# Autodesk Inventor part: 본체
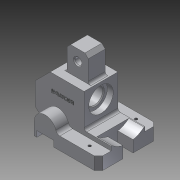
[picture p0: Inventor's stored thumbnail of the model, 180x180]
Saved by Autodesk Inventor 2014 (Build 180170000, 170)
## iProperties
Created: 2016-11
Part Number: 본체
Material: Aluminum 6061
Document SubType Name: Modeling
Designer: user
Density: 2.71 g/cm^3
Appearance: Aluminum - Flat
Author: user
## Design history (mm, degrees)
sketch "Sketch2"
  geometry: L1 (0, 0)-(63, 0); L2 (-13, 15)-(13, 15); L3 (-13, 15)-(-13, 0); L4 (0, 0)-(-13, 0); L5 (-10, 0)-(-10, 7); L6 (-10, 7)-(10, 7); L7 (10, 7)-(10, 0); L8 (13, 15)-(38.139, 15); L9 (-13, 0)-(-10, 0); L10 (63, 0)-(63, 15); L11 (38.139, 15)-(63, 15); A1 r 13 centre (0, 15) between (13, 15) and (-13, 15); 2 further points
  constraints: 22 end point, 7 perpendicular, 2 midpoint, 2 point on circle, 2 point on line, 1 centre point, 1 coincident, 1 collinear, 1 horizontal, 1 parallel, 1 tangent, 1 vertical alignment
  dimensions: "d0" = 26 diameter of A1; "d1" = 15 distance of L1.start A1.centre; "d2" = 7 distance of L5.start L5.end; "d3" = 20 distance of L5.end L6.end; "d4" = 63 distance of L1.end L1.start; "d5" = 15 distance of L1.end L10.end; "d6" = 3 distance between parallel lines of L5 L3
extrude "Extrusion1" new body sketch "Sketch2" stored distance "d7" = 70; taper "d8" = 0 deg
fillet "Fillet1" dims "d9" = 5
sketch "Sketch3"
  geometry: L1 (17.292, 15)-(63, 15) reference; L2 (63, 15)-(63, 0) reference; L3 (-13, 0)-(-13, 15) reference; L4 (63, 15)-(63, 20); L5 (-27, 12)-(-27, 42); L6 (31, 20)-(31, 60); L7 (26, 42)-(26, 60); L8 (-9, 60)-(31, 60); L9 (63, 0)-(10, 0) reference; L10 (-27, 12)-(-13, 12); L11 (-27, 42)-(31, 42); L12 (-27, 42)-(-9, 60); L13 (63, 15)-(17.292, 15) reference; L14 (31, 20)-(63, 20); A1 r 13 centre (0, 15) between (12.488, 18.611) and (-13, 15) reference; A2 r 5 centre (17.292, 20) between (12.488, 18.611) and (17.292, 15) reference; 3 further points
  constraints: 18 end point, 7 parallel, 5 point on line, 1 horizontal alignment, 1 perpendicular
  dimensions: "d10" = 5 distance of L4.end L1.end; "d11" = 90 distance between parallel lines of L2 L5; "d12" = 58 distance between parallel lines of L6 L5; "d13" = 5 distance between parallel lines of L6 L7; "d14" = 60 distance between parallel lines of L9 L8; "d15" = 48 distance between parallel lines of L10 L8; "d16" = 30 distance between parallel lines of L11 L10; "d17" = 45 deg angle of L12 L8
extrude "Extrusion2" join sketch "Sketch3" stored distance "d18" = 40; taper "d19" = 0 deg
chamfer "Chamfer1" distance "d20" = 4; stored, may be unused: second distance "d21" = 2, angle "d22" = 45 deg
sketch "Sketch5"
  geometry: L1 (55, -15)-(-15, -15) reference; C1 r 14.5 at (20, 27); 3 further points
  constraints: 1 centre point, 1 coincident, 1 midpoint, 1 vertical alignment
  dimensions: "d24" = 42 distance from line of L1 point (20, 27); "d25" = 29 diameter of C1
extrude "Extrusion3" cut sketch "Sketch5" distance "d26" = 7; taper "d27" = 0 deg
sketch "Sketch6"
  geometry: C1 r 14.5 at (0, 0) reference; C2 r 10 at (0, 0); 1 further point
  constraints: 1 centre point, 1 coincident
  dimensions: "d28" = 20 diameter of C2
extrude "Extrusion4" cut sketch "Sketch6" distance "d29" = 64; taper "d30" = 0 deg
chamfer "Chamfer2" distance "d31" = 1; stored, may be unused: second distance "d32" = 2, angle "d33" = 45 deg
sketch "Sketch4"
  geometry: L1 (31, 60)-(31, 20) reference; L2 (26, 90)-(26, 60); L3 (1, 90)-(26, 90); L4 (-9, 60)-(31, 60) reference; L5 (1, 90)-(1, 60); 2 further points
  constraints: 6 end point, 2 perpendicular, 2 point on line, 1 parallel
  dimensions: "d23" = 5 distance between parallel lines of L1 L2; "d34" = 90 distance from line of point (0, 0) L3; "d35" = 25 distance between parallel lines of L2 L5
extrude "Extrusion5" join sketch "Sketch4" stored distance "d36" = 20; taper "d37" = 0 deg
sketch "Sketch7"
  geometry: L1 (1, 90)-(1, 60) reference; L2 (31, 20)-(31, 60) reference; L3 (26, 60)-(1, 60) reference; 4 further points
  constraints: 1 midpoint
  dimensions: "d38" = 12.5 distance from line of point (13.5, 77) L1; "d77" = 17 distance from line of L3 point (13.5, 77)
hole "Hole1" sketch "Sketch7" at (13.5, 77) diameter "d39" = 8; stored, may be unused: countersink angle "d43" = 90 deg, drill point angle "d45" = 0 deg; dims "d40" = 6, "d41" = 4, "d42" = 2, "d44" = 8
chamfer "Chamfer3" distance "d46" = 1; stored, may be unused: second distance "d47" = 2, angle "d48" = 45 deg
chamfer "Chamfer4" distance "d49" = 4; stored, may be unused: second distance "d50" = 2, angle "d51" = 45 deg
sketch "Sketch10"
  geometry: L1 (45.708, 0)-(45.708, 15) reference; L2 (45.708, 55)-(45.708, 70) reference; L3 (45.708, 55)-(45.708, 15) reference; 4 further points
  constraints: 1 horizontal alignment, 1 midpoint
  dimensions: "d53" = 18 distance from line of L1 point (27.708, 7.5); "d54" = 18 distance from line of L2 point (27.708, 62.5); "d55" = 55 distance of point (27.708, 7.5) point (27.708, 62.5)
hole "Hole2" sketch "Sketch10" at (27.708, 62.5), (27.708, 7.5) diameter "d56" = 3.242; stored, may be unused: countersink angle "d60" = 90 deg, drill point angle "d62" = 0 deg; dims "d57" = 6, "d58" = 4, "d59" = 2, "d61" = 8
sketch "Sketch11"
  geometry: L1 (55, 20)-(15, 20) reference; L2 (29, -16.373)-(41, -16.373); L3 (41, -16.373)-(41, 13.627); L4 (29, 13.627)-(29, -16.373); L5 (29, -16.373)-(39.918, 13.42); L6 (41, -16.373)-(29.598, 14.741); C1 r 10 at (35, 42) reference; A1 r 29 centre (35, 42) between (16.106, 20) and (53.894, 20); 2 further points
  constraints: 10 end point, 5 point on circle, 4 point on line, 1 centre point, 1 coincident, 1 horizontal, 1 midpoint, 1 parallel, 1 perpendicular, 1 vertical alignment
  dimensions: "d63" = 12 distance of L2.start L2.end; "d64" = 58 diameter of A1; "d65" = 30 distance of L2.end L3.end
extrude "Extrusion6" cut sketch "Sketch11" distance "d66" = 18; taper "d67" = 0 deg
fillet "Fillet2" dims "d68" = 3
workplane "Work Plane1"
sketch "Sketch12"
  geometry: L1 (31, 23)-(31, 60) reference; L2 (31, 60)-(-9, 60) reference; 2 further points
  constraints: 1 other
  dimensions: "d70" = 25 distance from line of L1 point (6, 42); "d71" = 18 distance from line of point (6, 42) L2
emboss "Emboss1" sketch "Sketch12" dims "d0" = 26, "d1" = 15, "d2" = 7, "d3" = 20, "d4" = 63, "d5" = 15, "d6" = 3, "d72" = 0.5, "d73" = 0
chamfer "Chamfer5" distance "d74" = 5; stored, may be unused: second distance "d75" = 2, angle "d76" = 45 deg
body "Solid1"
other parameters: "d69" = 64.25
